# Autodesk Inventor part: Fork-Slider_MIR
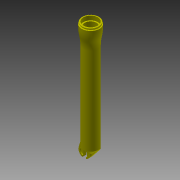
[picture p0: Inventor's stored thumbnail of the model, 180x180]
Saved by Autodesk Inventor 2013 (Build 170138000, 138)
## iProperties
Created: 2001-11
Part Number: Fork-Slider_MIR
Document SubType Name: Modeling
Designer: Autodesk, Inc.
Mass: 115.052 g
Surface Area: 625.893 cm^2
Volume: 115.052 cm^3
Density: 1 g/cm^3
Material: Generic
Author: Autodesk, Inc.
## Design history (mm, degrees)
derived "Fork-Slider.ipt"
  node "Sketch7"
  node "Sketch9"
  sketch "Sketch13"
    geometry: C1 r 3.034 at (0, 0) reference; A1 r 3.034 centre (0, 0) between (-2.458, 1.778) and (2.458, 1.778) reference
  workplane "Work Plane3"
  node "WorkPlane4"
  workplane "Work Plane8"
  node "WorkPlane5"
  node "WorkPlane1"
  node "WorkPlane2"
  node "WorkPlane3"
  node "WorkAxis1"
body "Solid1"
tag "TaggingFeature2"
workplane "Work Plane10"
workplane "Work Plane11"
workplane "Work Plane5"
workplane "Work Plane6"
feature "DerivedBody::Fork-Slider.ipt"
